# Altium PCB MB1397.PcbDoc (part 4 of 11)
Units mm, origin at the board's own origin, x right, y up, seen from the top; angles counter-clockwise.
Board outline 118.24 x 172.86 mm, 6 copper layers (Top Layer, L2_GND, L3_VCC, L4_SIG, L5_GND, Bottom Layer), stack 1.631 mm thick; 819 components, 632 nets, 2875 pads, 1523 vias.
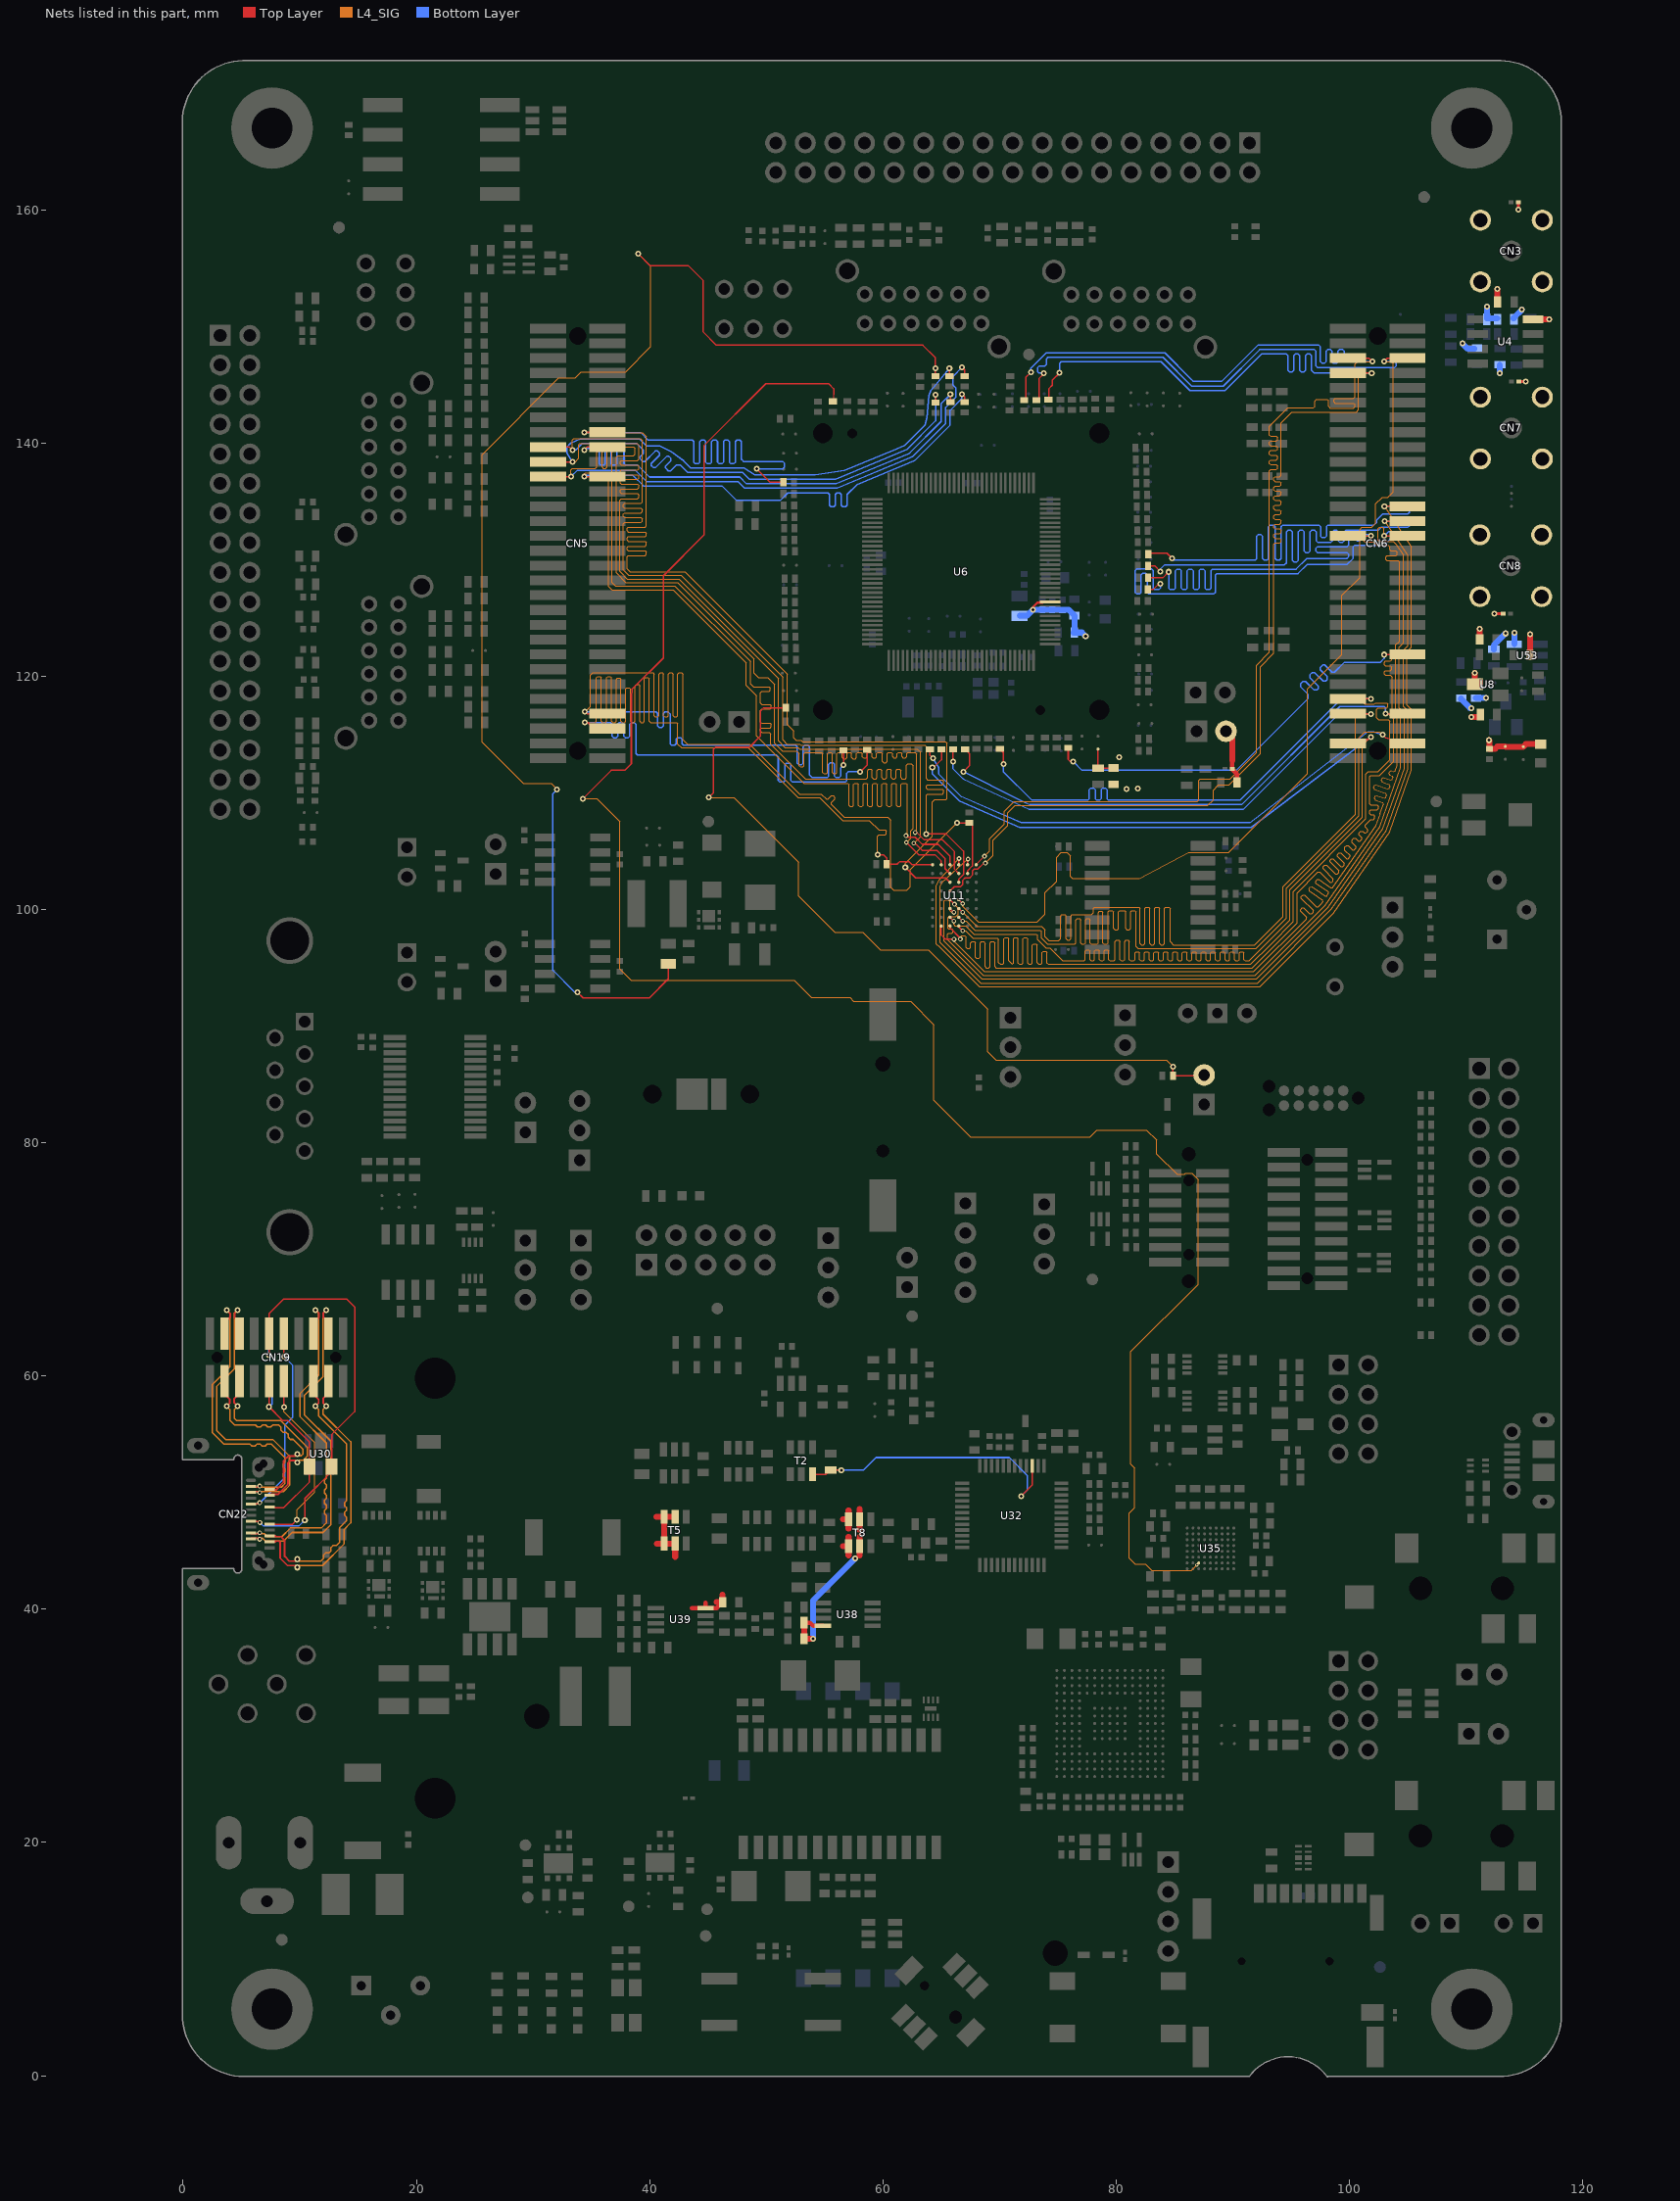
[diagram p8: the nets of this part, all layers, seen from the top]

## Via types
v1: diameter 0.508, hole 0.254, Top Layer to Bottom Layer, tented both sides, 1330 vias
v2: diameter 0.406, hole 0.203, Top Layer to Bottom Layer, tented both sides, 115 vias
v3: diameter 0.508, hole 0.254, Top Layer to Bottom Layer, 33 vias
v4: diameter 0.305, hole 0.152, Top Layer to Bottom Layer, tented both sides, 26 vias
v5: diameter 0.61, hole 0.305, Top Layer to Bottom Layer, tented both sides, 14 vias
v6: diameter 0.61, hole 0.33, Top Layer to Bottom Layer, tented both sides, 2 vias
v7: diameter 0.381, hole 0.203, Top Layer to Bottom Layer, tented both sides, 2 vias
v8: diameter 0.508, hole 0.203, Top Layer to Bottom Layer, tented both sides, 1 vias

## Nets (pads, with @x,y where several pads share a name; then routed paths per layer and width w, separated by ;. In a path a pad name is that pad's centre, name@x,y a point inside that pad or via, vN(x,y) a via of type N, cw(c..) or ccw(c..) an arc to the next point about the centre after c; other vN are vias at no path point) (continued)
A0: CN6.51 R136.2 U11.A3 | length 122.2
  Top Layer w0.127: U11.A3@66.499,98.585 66.5,98.504 v2(66.832,98.171) ; R136.2@70.029,113.765 70.33,113.462 v1(70.33,112.469) ; CN6.51@99.865,118.061 v1(101.826,118.059)
  L4_SIG w0.102: v2(66.832,98.171) 67.102,98.171 67.739,97.533 69.822,97.533 69.924,97.432 69.924,95.425 70.051,95.298 70.279,95.298 70.381,95.4 70.381,97.483 70.482,97.584 70.686,97.584 70.787,97.483 70.787,95.603 71.092,95.298 71.194,95.4 71.194,97.483 71.295,97.584 71.498,97.584 71.6,97.483 71.6,95.4 71.702,95.298 71.905,95.298 72.006,95.4 72.006,97.483 72.108,97.584 72.311,97.584 72.413,97.483 72.413,95.4 72.514,95.298 72.718,95.298 72.819,95.4 72.819,96.949 72.921,97.051 73.124,97.051 73.226,96.949 73.226,95.425 73.353,95.298 73.556,95.298 73.657,95.4 73.657,96.314 73.759,96.416 73.962,96.416 74.064,96.314 74.064,95.4 74.165,95.298 91.539,95.298 93.279,97.036 95.197,98.953 95.197,101.547 101.42,107.77 101.42,111.63 101.597,111.808 102.436,111.808 103.477,112.85 103.477,116.126 103.35,116.253 102.486,116.253 102.309,116.431 102.309,117.168 102.436,117.295 103.198,117.295 103.299,117.396 103.299,117.599 103.198,117.701 102.232,117.701 102.131,117.599 101.318,117.599 101.216,117.701 101.216,117.955 101.321,118.059 v1(101.826,118.059)
  Bottom Layer w0.127: v1(70.33,112.469) 70.33,111.808 72.768,109.37 77.564,109.37 77.691,109.497 77.691,110.284 77.818,110.411 78.072,110.411 78.199,110.284 78.199,109.497 78.326,109.37 78.58,109.37 78.707,109.497 78.707,110.284 78.834,110.411 79.088,110.411 79.215,110.284 79.215,109.497 79.342,109.37 90.602,109.37 99.291,118.059 v1(101.826,118.059)
A1: CN6.54 R138.2 U11.A4 | length 123
  Top Layer w0.127: U11.A4@65.749,98.585 65.748,98.438 66.634,97.551 v2(66.634,97.47) ; v1(66.901,111.808) 67.409,112.316 67.409,113.378 67.038,113.749 R138.2@67.039,113.748 ; v1(103.096,116.789) CN6.54@104.965,116.791
  L4_SIG w0.102: v2(66.634,97.47) 66.634,97.66 66.736,97.762 67.003,97.762 67.114,97.65 67.114,96.746 67.216,96.644 67.419,96.644 67.521,96.746 67.521,97.127 67.622,97.229 67.826,97.229 67.927,97.127 67.927,95.908 68.029,95.806 68.232,95.806 68.334,95.908 68.334,97.127 68.435,97.229 68.638,97.229 68.765,97.102 68.765,95.095 68.867,94.993 69.07,94.993 69.172,95.095 69.172,97.127 69.273,97.229 69.492,97.229 69.593,97.127 69.593,95.095 69.695,94.993 91.666,94.993 95.501,98.826 95.501,101.42 97.279,103.198 97.437,103.198 98.316,102.319 98.458,102.319 98.57,102.431 98.603,102.479 98.603,102.634 97.744,103.492 97.744,103.662 97.887,103.805 98.031,103.805 98.801,103.035 98.946,103.035 99.075,103.165 99.075,103.335 98.318,104.092 98.318,104.237 98.443,104.361 98.588,104.361 99.263,103.685 99.408,103.685 99.532,103.81 99.538,103.817 99.538,103.96 98.946,104.554 98.946,104.696 99.09,104.841 99.245,104.841 99.753,104.333 99.898,104.333 99.898,104.336 100.04,104.539 100.04,104.62 99.609,105.054 99.609,105.349 99.746,105.486 99.891,105.486 100.254,105.12 100.399,105.12 100.541,105.265 100.541,105.41 100.203,105.748 100.203,105.943 100.366,106.106 100.533,106.106 100.769,105.87 100.914,105.87 101.056,106.012 101.056,106.157 100.81,106.406 100.81,106.55 100.957,106.698 101.128,106.698 101.275,106.553 101.417,106.553 101.509,106.642 101.562,106.718 101.562,106.84 101.343,107.058 101.343,107.231 101.826,107.714 102.055,107.714 102.156,107.815 102.156,108.019 102.055,108.12 101.826,108.12 101.724,108.222 101.724,108.45 101.826,108.552 102.372,108.552 102.461,108.638 102.474,108.676 102.474,108.857 102.372,108.958 101.826,108.958 101.724,109.06 101.724,111.402 101.826,111.503 102.563,111.503 103.782,112.723 103.782,116.357 103.35,116.789 v1(103.096,116.789)
  Bottom Layer w0.127: v1(66.901,111.808) 71.643,109.416 72.573,108.989 90.76,108.989 99.17,117.399 102.969,117.399 103.096,117.272 v1(103.096,116.789)
A2: CN6.46 R132.2 U11.A5 | length 120.5
  Top Layer w0.127: U11.A5@64.999,98.585 64.999,97.81 65.364,97.445 v2(66.088,97.445) ; R132.2@75.888,113.85 75.888,112.855 76.045,112.697 v1(76.299,112.697) ; v1(102.984,121.857) 102.997,121.869 CN6.46@104.965,121.871
  L4_SIG w0.102: v2(66.088,97.445) 66.088,97.29 68.692,94.689 91.793,94.689 96.302,99.197 96.302,99.339 95.806,99.837 95.806,99.997 95.941,100.132 96.086,100.132 96.563,99.654 96.759,99.654 96.891,99.784 96.891,99.929 95.865,100.952 95.865,101.097 96.009,101.242 96.152,101.242 97.165,100.228 97.333,100.228 97.574,100.47 97.706,100.658 97.678,100.818 96.533,101.615 96.507,101.755 96.624,101.923 96.766,101.948 97.92,101.143 98.062,101.168 98.186,101.346 98.153,101.534 97.122,102.253 97.122,102.431 97.259,102.568 97.379,102.568 98.377,101.874 98.555,101.874 102.283,107.218 102.639,108.227 102.636,108.227 102.913,109.004 102.837,109.164 102.199,109.39 102.136,109.52 102.205,109.71 102.334,109.774 102.994,109.54 103.124,109.604 103.182,109.771 103.091,109.964 102.131,110.305 102.07,110.432 102.138,110.625 102.268,110.686 103.264,110.335 103.406,110.404 103.454,110.538 103.368,110.719 102.791,110.924 102.728,111.051 102.796,111.244 102.926,111.305 103.541,111.089 103.67,111.153 103.726,111.305 103.662,111.435 103.441,111.511 103.381,111.641 103.449,111.834 103.579,111.895 103.8,111.818 103.929,111.879 104.087,112.329 104.087,116.609 103.655,117.041 103.655,119.931 103.508,120.079 103.096,120.079 102.994,120.18 102.994,120.383 103.096,120.485 103.508,120.485 103.609,120.587 103.609,120.79 103.508,120.891 103.096,120.891 102.994,120.993 102.994,121.196 103.096,121.298 103.508,121.298 103.609,121.399 103.609,121.752 103.508,121.854 v1(102.984,121.857)
  Bottom Layer w0.127: v1(76.299,112.697) 77.066,111.93 90.303,111.93 96.463,118.09 96.463,118.446 95.796,119.113 95.796,119.331 96.008,119.543 96.241,119.543 96.962,118.821 97.194,118.821 97.312,118.939 97.312,119.175 96.596,119.891 96.596,120.106 96.784,120.294 97.028,120.294 97.739,119.583 97.956,119.583 98.095,119.722 98.095,119.964 97.495,120.564 97.495,120.749 97.724,120.978 97.869,120.978 98.501,120.345 98.718,120.345 99.579,121.206 102.653,121.206 102.984,121.538 v1(102.984,121.857)
A3: CN6.58 R139.2 U11.B3 | length 123.1
  Top Layer w0.127: R139.2@64.028,113.723 64.028,113.233 v1(64.285,112.977) ; U11.B3@66.499,99.335 v2(66.832,99.002) ; v1(102.842,114.983) 103.096,114.729 CN6.58@104.965,114.249
  L4_SIG w0.102: v2(66.832,99.002) 67.135,99.002 67.902,98.235 73.464,98.235 73.581,98.118 73.581,97.533 74.089,97.025 76.449,97.025 76.551,97.127 76.551,99.108 76.652,99.21 76.855,99.21 76.957,99.108 76.957,97.127 77.059,97.025 77.262,97.025 77.363,97.127 77.363,99.108 77.465,99.21 77.668,99.21 77.77,99.108 77.77,97.127 77.871,97.025 78.356,97.025 78.458,97.127 78.458,99.743 78.56,99.845 78.763,99.845 78.864,99.743 78.864,97.127 78.966,97.025 79.195,97.025 79.296,97.127 79.296,99.794 79.398,99.896 79.652,99.896 79.753,99.794 79.753,98.372 79.88,98.245 80.109,98.245 80.211,98.346 80.211,99.794 80.312,99.896 80.719,99.896 80.82,99.794 80.82,98.372 80.922,98.27 81.125,98.27 81.227,98.372 81.227,99.794 81.328,99.896 81.582,99.896 81.684,99.794 81.684,96.848 81.862,96.67 91.996,96.67 94.587,99.261 94.587,101.826 100.81,108.047 100.81,114.729 101.318,115.237 102.588,115.237 v1(102.842,114.983)
  Bottom Layer w0.127: v1(64.285,112.977) 64.767,112.189 64.767,111.625 66.695,109.698 71.854,107.439 91.478,107.439 101.572,115.237 102.08,115.237 v1(102.842,114.983)
A4: CN6.57 R140.2 U11.B4 | length 124.3
  Top Layer w0.127: v1(64.234,112.177) 64.348,112.177 65.016,112.845 R140.2@65.016,113.723 ; U11.B4@65.749,99.335 65.75,99.334 v2(66.083,99.002) ; CN6.57@99.865,114.251 100.965,114.249 101.318,114.602 101.636,114.602 v1(101.826,114.793)
  L4_SIG w0.102: v2(66.083,99.002) 66.083,98.704 66.185,98.603 67.102,98.603 67.815,97.889 73.152,97.889 73.251,97.79 73.251,97.432 73.962,96.721 74.292,96.721 75.41,95.603 77.239,95.603 77.34,95.705 77.34,96.441 77.442,96.543 77.645,96.543 77.747,96.441 77.747,95.705 77.848,95.603 78.052,95.603 78.153,95.705 78.153,96.441 78.255,96.543 78.458,96.543 78.56,96.441 78.56,95.705 78.661,95.603 78.864,95.603 78.966,95.705 78.966,96.441 79.068,96.543 79.271,96.543 79.372,96.441 79.372,95.705 79.474,95.603 79.814,95.603 79.916,95.705 79.916,97.254 80.018,97.356 80.221,97.356 80.322,97.254 80.322,95.705 80.424,95.603 80.627,95.603 80.729,95.705 80.729,97.254 80.83,97.356 81.034,97.356 81.135,97.254 81.135,95.705 81.237,95.603 81.504,95.603 81.605,95.705 81.605,96.263 81.707,96.365 81.91,96.365 82.012,96.263 82.012,95.705 82.113,95.603 82.316,95.603 82.418,95.705 82.418,96.263 82.52,96.365 82.723,96.365 82.824,96.263 82.824,95.705 82.926,95.603 83.129,95.603 83.231,95.705 83.231,96.263 83.332,96.365 83.536,96.365 83.637,96.263 83.637,95.705 83.739,95.603 83.942,95.603 84.044,95.705 84.044,96.263 84.145,96.365 84.348,96.365 84.45,96.263 84.45,95.705 84.552,95.603 84.755,95.603 84.856,95.705 84.856,96.263 84.958,96.365 85.161,96.365 85.263,96.263 85.263,95.705 85.364,95.603 85.568,95.603 85.669,95.705 85.669,96.263 85.771,96.365 85.974,96.365 86.076,96.263 86.076,95.705 86.177,95.603 86.38,95.603 86.482,95.705 86.482,96.263 86.584,96.365 86.787,96.365 86.888,96.263 86.888,95.705 86.99,95.603 87.193,95.603 87.295,95.705 87.295,96.263 87.396,96.365 87.6,96.365 87.701,96.263 87.701,95.705 87.803,95.603 88.006,95.603 88.108,95.705 88.108,96.263 88.209,96.365 88.412,96.365 88.514,96.263 88.514,95.705 88.616,95.603 88.819,95.603 88.92,95.705 88.92,96.263 89.022,96.365 89.225,96.365 89.327,96.263 89.327,95.705 89.428,95.603 89.632,95.603 89.733,95.705 89.733,96.263 89.835,96.365 90.038,96.365 90.14,96.263 90.14,95.705 90.241,95.603 90.444,95.603 90.546,95.705 90.546,96.263 90.648,96.365 90.851,96.365 90.952,96.263 90.952,95.705 91.054,95.603 91.415,95.603 94.892,99.08 94.892,101.699 101.115,107.922 101.115,114.079 v1(101.826,114.793)
  Bottom Layer w0.127: v1(64.234,112.177) 64.234,111.62 66.553,109.301 71.727,107.033 91.575,107.033 v1(101.826,114.793)
A5: CN6.53 R137.2 U11.C3 | length 123.4
  Top Layer w0.127: v1(66.015,112.697) R137.2@66.015,113.748 ; U11.C3@66.499,100.085 66.5,100.086 v2(66.832,99.753) ; CN6.53@99.865,116.791 101.798,116.789 v1(101.826,116.761)
  L4_SIG w0.102: v2(66.832,99.753) 68.044,98.539 73.591,98.539 73.886,98.245 73.886,97.66 74.216,97.33 75.08,97.33 75.232,97.483 75.232,99.438 75.334,99.54 75.603,99.54 75.705,99.438 75.705,97.483 75.806,97.381 76.01,97.381 76.111,97.483 76.111,99.438 76.213,99.54 77.874,99.54 78.052,99.718 78.052,100.099 78.153,100.2 81.945,100.2 82.047,100.099 82.047,97.076 82.149,96.975 82.352,96.975 82.453,97.076 82.453,100.099 82.555,100.2 82.786,100.2 82.888,100.099 82.888,97.076 82.989,96.975 83.193,96.975 83.294,97.076 83.294,100.099 83.396,100.2 83.624,100.2 83.726,100.099 83.726,97.076 83.828,96.975 84.031,96.975 84.132,97.076 84.132,100.099 84.234,100.2 84.529,100.2 84.63,100.099 84.63,97.229 84.884,96.975 91.869,96.975 94.282,99.388 94.282,101.951 100.505,108.174 100.505,116.456 100.81,116.761 v1(101.826,116.761)
  Bottom Layer w0.127: v1(66.015,112.697) 66.015,112.06 66.901,111.173 72.489,108.608 89.99,108.608 90.914,108.608 98.778,116.472 99.068,116.761 v1(101.826,116.761)
A6: CN6.30 R93.2 U11.C4 | length 122.1
  Top Layer w0.127: U11.C4@65.749,100.085 65.75,100.086 v2(66.083,99.753) ; R93.2@82.712,127.455 83.182,127.455 83.665,127.937 v1(83.792,127.937) ; v1(102.969,132.029) CN6.30@104.965,132.031
  L4_SIG w0.102: v2(66.083,99.753) 65.86,99.753 65.733,99.88 65.733,100.708 65.606,100.835 65.334,100.835 65.225,100.726 65.225,97.29 68.463,94.054 92.022,94.054 98.176,100.208 102.885,106.959 104.696,112.093 104.696,116.863 104.264,117.295 104.264,122.502 104.62,122.857 104.62,130.371 103.998,131.303 103.756,131.544 102.563,131.544 102.461,131.646 102.461,132.636 102.588,132.763 102.842,132.763 102.969,132.636 v1(102.969,132.029)
  Bottom Layer w0.127: v1(83.792,127.937) 83.792,127.556 83.665,127.429 83.284,127.429 83.157,127.556 83.157,129.08 83.03,129.207 81.755,129.207 81.633,129.085 81.633,127.175 81.76,127.048 82.014,127.048 82.141,127.175 82.141,128.699 82.268,128.826 82.522,128.826 82.649,128.699 82.649,127.175 82.776,127.048 88.364,127.048 88.504,127.188 88.504,128.674 88.631,128.801 95.583,128.801 96.37,129.588 99.794,129.588 100.322,130.117 100.322,131.112 100.449,131.239 102.969,131.239 103.477,131.747 104.874,131.747 105.001,131.874 105.001,132.255 104.874,132.382 103.322,132.382 v1(102.969,132.029)
A7: CN6.29 R89.2 U11.D4 | length 122.2
  Top Layer w0.127: U11.D4@65.749,100.835 65.75,100.835 v2(66.134,100.449) ; R89.2@82.742,128.441 83.99,128.44 v1(84.503,128.953) ; CN6.29@99.865,132.031 v1(101.826,132.029)
  L4_SIG w0.102: v2(66.134,100.449) 66.469,100.114 66.469,99.591 66.266,99.388 65.656,99.388 65.557,99.289 65.557,98.4 65.606,98.351 65.91,98.351 66.012,98.25 66.012,98.047 65.91,97.945 65.606,97.945 65.527,97.866 65.527,97.419 65.661,97.285 68.59,94.358 91.895,94.358 97.912,100.376 102.621,107.125 104.391,112.144 104.391,116.736 103.96,117.168 103.96,122.679 104.29,123.01 104.29,129.791 104.163,129.918 103.218,129.918 103.116,130.02 103.116,130.223 103.218,130.325 103.985,130.325 104.092,130.432 104.092,130.614 103.95,130.757 103.553,130.757 103.452,130.858 103.452,131.112 103.327,131.239 102.385,131.239 102.105,131.519 101.318,131.519 101.191,131.646 101.191,131.9 101.321,132.029 v1(101.826,132.029)
  Bottom Layer w0.127: v1(84.503,128.953) 84.503,127.556 84.63,127.429 84.948,127.429 85.075,127.556 85.075,129.055 85.202,129.182 85.456,129.182 85.583,129.055 85.583,127.556 85.71,127.429 85.964,127.429 86.091,127.556 86.091,129.055 86.218,129.182 86.472,129.182 86.599,129.055 86.599,127.556 86.726,127.429 86.98,127.429 87.107,127.556 87.107,129.055 87.234,129.182 87.488,129.182 87.615,129.055 87.615,127.556 87.742,127.429 87.996,127.429 88.123,127.556 88.123,129.055 88.25,129.182 95.425,129.182 96.34,130.096 99.764,130.096 99.941,130.277 99.941,130.457 99.794,130.604 97.254,130.604 97.127,130.731 97.127,130.985 97.254,131.112 99.794,131.112 99.921,131.239 99.921,132.001 100.048,132.128 100.396,132.128 100.523,132.001 100.523,131.747 100.65,131.62 100.904,131.62 101.031,131.747 101.031,132.001 101.158,132.128 101.727,132.128 v1(101.826,132.029)
A8: CN6.28 R88.2 U11.H2 | length 124.6
  Top Layer w0.127: U11.H2@67.249,103.835 67.249,104.282 v2(67.295,104.328) ; R88.2@82.737,129.457 83.315,129.456 v1(83.792,128.979) ; v1(103.033,133.299) CN6.28@104.965,133.301
  L4_SIG w0.102: v2(67.295,104.328) 65.072,102.324 64.92,101.94 64.92,97.155 68.374,93.698 92.098,93.698 98.443,100.046 103.149,106.792 105.001,112.039 105.001,117.015 104.62,117.396 104.62,122.222 105.001,122.603 105.001,130.35 v1(103.033,133.299)
  Bottom Layer w0.127: v1(83.792,128.979) 83.792,129.192 84.163,129.563 94.435,129.563 94.587,129.715 94.587,132.382 94.714,132.509 94.981,132.509 95.108,132.382 95.108,129.936 95.235,129.809 95.489,129.809 95.616,129.936 95.616,132.382 95.743,132.509 95.997,132.509 96.124,132.382 96.124,130.731 96.251,130.604 96.505,130.604 96.632,130.731 96.632,132.382 96.759,132.509 97.013,132.509 97.14,132.382 97.14,131.62 97.267,131.493 98.397,131.493 98.524,131.62 98.524,132.382 98.651,132.509 98.905,132.509 99.032,132.382 99.032,131.62 99.159,131.493 99.413,131.493 99.54,131.62 99.54,132.382 99.667,132.509 102.461,132.509 102.715,132.763 105.001,132.763 105.128,132.89 105.128,133.144 104.973,133.299 v1(103.033,133.299)
A9: CN6.26 R87.2 U11.H3 | length 126.6
  Top Layer w0.127: U11.H3@66.499,103.835 66.5,104.346 v2(66.52,104.366) ; R87.2@82.755,130.468 82.756,130.467 82.842,130.553 84.351,130.553 v1(84.808,130.096) ; v1(102.994,134.569) CN6.26@104.965,134.571
  L4_SIG w0.102: v2(66.52,104.366) 64.806,102.527 64.59,101.996 64.59,97.053 64.821,96.822 68.247,93.393 92.326,93.393 98.636,99.7 103.444,106.655 105.306,111.933 105.306,117.142 104.925,117.523 104.925,122.095 105.306,122.476 105.306,131.112 v1(102.994,134.569)
  Bottom Layer w0.127: v1(84.808,130.096) 84.935,129.969 91.92,129.969 92.047,130.096 92.047,132.001 92.174,132.128 92.428,132.128 92.555,132.001 92.555,130.096 92.682,129.969 92.936,129.969 93.063,130.096 93.063,132.827 93.19,132.954 93.508,132.954 93.635,132.827 93.635,130.096 93.762,129.969 94.016,129.969 94.143,130.096 94.143,132.827 94.27,132.954 97.394,132.954 97.521,132.827 97.521,132.001 97.648,131.874 97.902,131.874 98.029,132.001 98.029,132.827 98.156,132.954 102.083,132.954 102.334,133.205 102.334,133.398 102.842,133.906 105.001,133.906 105.128,134.033 105.128,134.414 104.973,134.569 v1(102.994,134.569)
A10: CN5.22 R48.2 U11.H4 | length 124.2
  Top Layer w0.127: v1(34.389,137.112) 36.386,137.112 CN5.22@36.385,137.111 ; v2(61.973,106.335) 61.986,106.335 62.123,106.195 62.766,106.195 63.376,105.585 64.742,105.585 65.748,104.582 U11.H4@65.749,103.835 ; v1(66.761,144.168) 66.774,144.168 67.003,143.942 R48.2@67.003,143.524
  L4_SIG w0.102: v1(34.389,137.112) 34.389,137.335 34.491,137.437 36.345,137.437 36.472,137.31 36.472,127.683 36.751,127.404 42.034,127.404 48.283,121.155 48.283,119.2 49.146,118.336 49.146,114.907 53.236,110.818 56.982,110.818 57.084,110.716 57.084,108.938 57.186,108.836 57.389,108.836 57.49,108.938 57.49,110.716 57.592,110.818 57.795,110.818 57.897,110.716 57.897,108.938 57.998,108.836 58.202,108.836 58.303,108.938 58.303,110.716 58.405,110.818 58.608,110.818 58.71,110.716 58.71,108.938 58.811,108.836 59.014,108.836 59.116,108.938 59.116,110.716 59.218,110.818 59.421,110.818 59.522,110.716 59.522,108.938 59.624,108.836 59.827,108.836 59.929,108.938 59.929,110.716 60.03,110.818 60.234,110.818 60.335,110.716 60.335,108.938 60.437,108.836 60.64,108.836 60.742,108.938 60.742,110.716 60.843,110.818 61.046,110.818 61.148,110.716 61.148,108.938 61.25,108.836 61.453,108.836 61.554,108.938 61.554,110.716 61.656,110.818 61.973,110.818 62.075,110.716 62.075,106.436 v2(61.973,106.335)
  Bottom Layer w0.127: v1(34.389,137.112) 34.486,137.208 38.58,137.208 39.469,136.319 46.2,136.319 47.445,135.075 51.204,135.075 51.839,135.71 55.281,135.71 55.408,135.583 55.408,134.668 55.535,134.541 55.789,134.541 55.916,134.668 55.916,135.583 56.043,135.71 56.297,135.71 56.424,135.583 56.424,134.668 56.551,134.541 56.805,134.541 56.932,134.668 56.932,135.583 57.788,136.439 62.71,138.478 65.758,141.526 65.758,142.796 66.761,143.8 v1(66.761,144.168)
A11: CN5.21 R28.2 U11.H5 | length 121.6
  Top Layer w0.127: CN5.21@31.285,137.111 33.244,137.109 v1(33.246,137.112) ; v2(62.012,105.75) 63.063,104.696 64.455,104.696 64.999,104.155 U11.H5@64.999,103.835 ; v1(66.774,146.479) 67.003,146.253 R28.2@67.003,145.738
  L4_SIG w0.102: v1(33.246,137.112) 33.246,137.701 33.373,137.828 35.354,137.828 35.456,137.93 35.456,139.207 35.593,139.344 35.809,139.344 35.928,139.225 35.928,137.93 36.03,137.828 36.236,137.828 36.335,137.93 36.335,139.273 36.406,139.344 36.675,139.344 36.777,139.243 36.777,128.039 37.081,127.734 42.161,127.734 48.638,121.257 48.638,119.352 48.892,119.098 50.239,119.098 50.34,118.996 50.34,118.793 50.239,118.692 49.604,118.692 49.502,118.59 49.502,117.686 49.604,117.584 50.315,117.584 50.416,117.483 50.416,117.279 50.315,117.178 49.604,117.178 49.502,117.076 49.502,116.083 49.604,115.981 50.315,115.981 50.416,115.88 50.416,115.677 50.315,115.575 49.604,115.575 49.502,115.473 49.502,115.288 49.629,115.161 50.239,115.161 50.366,115.034 50.366,114.17 53.337,111.199 58.58,111.199 58.682,111.3 58.682,111.91 58.783,112.011 58.986,112.011 59.088,111.91 59.088,111.3 59.19,111.199 59.393,111.199 59.494,111.3 59.494,111.91 59.596,112.011 59.799,112.011 59.901,111.91 59.901,111.3 60.002,111.199 60.206,111.199 60.307,111.3 60.307,111.91 60.409,112.011 60.612,112.011 60.714,111.91 60.714,111.3 60.815,111.199 61.018,111.199 61.12,111.3 61.12,111.91 61.222,112.011 61.425,112.011 61.526,111.91 61.526,111.3 61.628,111.199 61.923,111.199 62.024,111.3 62.024,112.367 62.151,112.494 62.431,112.494 62.583,112.342 62.583,106.962 62.38,106.759 62.38,106.119 v2(62.012,105.75)
  Bottom Layer w0.127: v1(33.246,137.112) 33.802,137.668 38.755,137.668 39.723,136.7 47.567,136.7 48.151,136.116 56.017,136.116 56.078,136.141 56.083,136.141 62.319,138.737 62.504,138.814 65.377,141.686 65.377,143.05 66.266,143.939 66.266,144.711 66.012,144.963 66.012,145.717 v1(66.774,146.479)
A12: CN5.18 R50.2 U11.G3 | length 125
  Top Layer w0.127: v1(34.389,139.398) 34.641,139.649 CN5.18@36.385,139.651 ; v2(62.761,106.601) 62.901,106.601 63.533,105.966 65.121,105.966 66.139,104.95 66.139,103.444 66.5,103.086 U11.G3@66.499,103.085 ; R50.2@65.786,143.503 v1(65.786,144.16)
  L4_SIG w0.102: v1(34.389,139.398) 34.641,139.649 38.603,139.649 38.732,139.52 38.732,139.037 38.605,138.91 37.259,138.91 37.132,138.783 37.132,128.854 37.948,128.039 42.39,128.039 48.943,121.486 48.943,120.266 49.324,119.885 50.112,119.885 50.721,119.276 50.721,114.247 51.382,113.586 52.601,113.586 52.829,113.358 52.829,112.342 52.931,112.24 53.134,112.24 53.236,112.342 53.236,113.358 53.337,113.459 54.745,113.459 54.846,113.358 54.846,111.757 54.948,111.656 55.151,111.656 55.253,111.757 55.253,113.358 55.354,113.459 55.557,113.459 55.659,113.358 55.659,111.757 55.761,111.656 55.964,111.656 56.065,111.757 56.065,113.358 56.167,113.459 56.408,113.459 56.51,113.358 56.51,113.027 56.612,112.926 56.815,112.926 56.916,113.027 56.916,113.358 57.018,113.459 57.221,113.459 57.323,113.358 57.323,113.027 57.424,112.926 57.628,112.926 57.729,113.027 57.729,113.358 57.831,113.459 58.143,113.459 58.245,113.358 58.245,113.078 58.346,112.977 58.55,112.977 58.651,113.078 58.651,113.358 58.753,113.459 58.956,113.459 59.058,113.358 59.058,113.078 59.159,112.977 59.362,112.977 59.464,113.078 59.464,113.358 59.566,113.459 59.855,113.459 59.957,113.358 59.957,112.697 60.058,112.596 60.261,112.596 60.363,112.697 60.363,113.358 60.465,113.459 60.719,113.459 60.82,113.358 60.82,113.104 60.922,113.002 61.125,113.002 61.227,113.104 61.227,113.358 61.328,113.459 61.531,113.459 61.633,113.358 61.633,113.104 61.735,113.002 61.938,113.002 62.039,113.104 62.039,113.358 62.141,113.459 62.761,113.459 62.888,113.332 62.888,106.728 v2(62.761,106.601)
  Bottom Layer w0.127: v1(34.389,139.398) 34.516,139.525 35.55,139.525 35.677,139.398 35.677,138.224 35.804,138.097 36.058,138.097 36.185,138.224 36.185,139.398 36.312,139.525 36.566,139.525 36.693,139.398 36.693,138.224 36.82,138.097 37.074,138.097 37.201,138.224 37.201,139.398 37.328,139.525 37.673,139.525 37.798,139.398 37.798,138.245 37.945,138.097 38.966,138.097 39.982,137.081 47.724,137.081 48.308,136.497 55.941,136.497 56.002,136.522 56.007,136.522 62.184,139.093 62.288,139.136 64.996,141.846 64.996,143.37 v1(65.786,144.16)
A13: CN5.19 R27.2 U11.G4 | length 122.1
  Top Layer w0.127: CN5.19@31.285,138.381 33.371,138.379 v1(33.373,138.382) ; v2(62.634,105.687) 62.735,105.687 63.345,105.077 64.615,105.077 65.331,104.364 65.331,103.505 65.75,103.086 U11.G4@65.749,103.085 ; R27.2@65.703,145.738 v1(65.702,146.393)
  L4_SIG w0.102: v1(33.373,138.382) 33.607,138.382 33.909,138.684 33.909,139.852 34.011,139.954 38.908,139.954 39.063,139.799 39.063,138.605 38.961,138.504 37.564,138.504 37.462,138.402 37.462,138.199 37.564,138.097 38.961,138.097 39.063,137.996 39.063,137.792 38.961,137.691 37.564,137.691 37.462,137.589 37.462,137.386 37.564,137.284 38.961,137.284 39.063,137.183 39.063,136.98 38.961,136.878 37.564,136.878 37.462,136.776 37.462,136.573 37.564,136.472 38.961,136.472 39.063,136.37 39.063,136.167 38.961,136.065 37.564,136.065 37.462,135.964 37.462,135.76 37.564,135.659 38.961,135.659 39.063,135.557 39.063,135.329 38.936,135.202 37.564,135.202 37.437,135.075 37.437,128.981 38.072,128.344 42.517,128.344 51.051,119.809 51.051,114.45 51.613,113.889 52.726,113.889 52.851,113.764 62.939,113.764 63.218,113.485 63.218,106.22 62.685,105.687 v2(62.634,105.687)
  Bottom Layer w0.127: v1(33.373,138.382) 32.893,139.126 32.893,139.649 33.246,140.002 34.008,140.335 39.136,140.335 39.723,139.748 40.866,139.748 41.882,139.24 42.898,138.478 43.533,137.843 48.105,137.843 48.994,137.284 54.206,137.284 56.693,137.635 60.894,139.383 61.854,139.781 63.599,141.526 63.772,142.161 63.944,144.066 64.12,144.516 v1(65.702,146.393)
A14: CN5.17 R53.2 U11.F3 | length 125.3
  Top Layer w0.127: CN5.17@31.285,139.651 33.122,139.649 v1(33.373,139.398) ; v1(63.726,106.474) 65.425,106.474 66.901,105.001 66.901,102.994 66.5,102.593 U11.F3@66.499,102.335 ; R53.2@64.501,143.474 64.501,143.474 64.516,143.49 v1(64.516,144.145)
  L4_SIG w0.102: v1(33.373,139.398) 33.373,140.256 33.475,140.358 39.215,140.358 39.367,140.205 39.367,134.917 39.266,134.816 37.843,134.816 37.742,134.714 37.742,134.511 37.843,134.409 39.266,134.409 39.367,134.308 39.367,134.104 39.266,134.003 37.843,134.003 37.742,133.901 37.742,133.698 37.843,133.596 39.266,133.596 39.367,133.495 39.367,133.292 39.266,133.19 37.843,133.19 37.742,133.088 37.742,129.106 38.199,128.648 42.695,128.648 51.407,119.936 51.407,114.551 51.768,114.191 52.851,114.191 52.973,114.069 63.599,114.069 63.726,113.942 63.726,111.214 63.828,111.115 65.098,111.115 65.199,111.011 65.199,110.808 65.098,110.706 63.828,110.706 63.726,110.607 63.726,110.401 63.828,110.3 65.098,110.3 65.199,110.198 65.199,109.995 65.098,109.893 63.828,109.893 63.726,109.792 v1(63.726,106.474)
  Bottom Layer w0.127: v1(33.373,139.398) 33.658,139.398 34.214,139.954 38.882,139.954 39.469,139.367 39.469,139.113 39.177,138.821 39.177,138.641 39.406,138.412 39.586,138.412 40.485,139.314 40.665,139.314 40.846,139.134 40.846,138.953 40.137,138.245 40.137,138.064 40.315,137.886 40.495,137.886 41.458,138.849 41.638,138.849 41.819,138.669 41.819,138.488 41.364,138.034 41.364,137.853 41.603,137.615 41.78,137.615 42.263,138.097 42.644,138.097 43.279,137.462 47.978,137.462 48.562,136.878 55.865,136.878 55.926,136.903 55.931,136.903 62.073,139.459 64.516,141.905 v1(64.516,144.145)
A15: CN5.16 R68.2 U11.F4 | length 122.8
  Top Layer w0.127: v1(34.392,140.891) 34.42,140.919 CN5.16@36.385,140.921 ; v1(49.185,137.78) 50.34,136.627 R68.2@51.468,136.627 ; v1(61.923,103.604) 62.812,102.715 65.369,102.715 65.75,102.334 U11.F4@65.749,102.335
  L4_SIG w0.102: v1(34.392,140.891) 39.367,140.891 39.723,140.536 39.723,132.885 39.621,132.784 38.174,132.784 38.072,132.682 38.072,132.479 38.174,132.377 39.621,132.377 39.723,132.276 39.723,132.072 39.621,131.971 38.174,131.971 38.072,131.869 38.072,131.666 38.174,131.564 39.621,131.564 39.723,131.463 39.723,131.26 39.621,131.158 38.174,131.158 38.072,131.056 38.072,130.853 38.174,130.752 39.621,130.752 39.723,130.65 39.723,130.447 39.621,130.345 38.174,130.345 38.072,130.244 38.072,129.207 38.326,128.953 43.025,128.953 51.788,120.19 51.788,115.872 52.336,115.325 52.336,114.717 52.56,114.493 52.976,114.493 53.096,114.374 65.377,114.374 65.504,114.247 65.504,109.522 65.402,109.421 64.437,109.421 64.234,109.217 64.234,106.271 61.923,103.96 v1(61.923,103.604)
  Bottom Layer w0.127: v1(34.392,140.891) 39.215,140.891 39.85,140.256 43.66,140.256 43.787,140.129 43.787,138.351 43.914,138.224 44.168,138.224 44.295,138.351 44.295,140.129 44.422,140.256 44.676,140.256 44.803,140.129 44.803,138.351 44.93,138.224 45.184,138.224 45.311,138.351 45.311,140.129 45.438,140.256 45.692,140.256 45.819,140.129 45.819,138.351 45.946,138.224 46.2,138.224 46.327,138.351 46.327,140.129 46.454,140.256 46.708,140.256 46.835,140.129 46.835,138.351 46.962,138.224 47.216,138.224 47.343,138.351 47.343,140.129 47.47,140.256 47.724,140.256 47.851,140.129 47.851,138.605 48.042,138.415 51.407,138.415 51.534,138.288 51.534,137.907 51.407,137.78 v1(49.185,137.78)
A16: CN6.7 R39.2 U11.E4 | length 122.9
  Top Layer w0.127: U11.E4@65.749,101.585 66.116,101.953 66.647,101.953 66.85,102.156 66.85,102.512 67.053,102.715 67.434,102.715 67.663,102.944 67.663,103.299 67.841,103.477 68.146,103.477 68.654,103.985 v2(68.781,103.985) ; R39.2@74.247,143.607 74.247,144.681 74.521,144.955 74.521,145.387 75.143,146.009 v1(75.143,146.035) ; CN6.7@99.865,146.001 99.865,146.002 v1(101.902,146.002)
  L4_SIG w0.102: v2(68.781,103.985) 69.441,104.645 69.441,105.926 70.711,107.196 70.711,108.278 71.346,108.913 87.831,108.913 88.323,109.403 88.323,110.244 88.755,110.673 89.667,110.673 92.37,113.375 92.37,120.818 93.52,121.968 93.52,131.315 93.622,131.417 94.028,131.417 94.13,131.519 94.13,131.722 94.028,131.823 93.622,131.823 93.52,131.925 93.52,132.128 93.622,132.23 94.028,132.23 94.13,132.331 94.13,132.535 94.028,132.636 93.622,132.636 93.52,132.738 93.52,132.941 93.622,133.043 94.028,133.043 94.13,133.144 94.13,133.347 94.028,133.449 93.622,133.449 93.52,133.551 93.52,133.754 93.622,133.855 94.028,133.855 94.13,133.957 94.13,134.16 94.028,134.262 93.622,134.262 93.52,134.363 93.52,134.567 93.622,134.668 94.028,134.668 94.13,134.77 94.13,134.973 94.028,135.075 93.622,135.075 93.52,135.176 93.52,135.379 93.622,135.481 94.028,135.481 94.13,135.583 94.13,135.786 94.028,135.887 93.622,135.887 93.52,135.989 93.52,136.192 93.622,136.294 94.028,136.294 94.13,136.395 94.13,136.599 94.028,136.7 93.622,136.7 93.52,136.802 93.52,137.005 93.622,137.107 94.028,137.107 94.13,137.208 94.13,141.704 95.07,142.644 100.581,142.644 100.785,142.847 100.785,145.768 101.018,146.002 v1(101.902,146.002)
  Bottom Layer w0.127: v1(75.143,146.035) 75.143,146.835 75.27,146.962 83.853,146.962 86.317,144.498 89.334,144.498 92.459,147.622 94.587,147.622 94.714,147.495 94.714,146.225 94.841,146.098 95.095,146.098 95.222,146.225 95.222,147.495 95.349,147.622 95.603,147.622 95.73,147.495 95.73,146.225 95.857,146.098 96.111,146.098 96.238,146.225 96.238,147.495 96.365,147.622 96.619,147.622 96.746,147.495 96.746,146.225 96.97,146.002 v1(101.902,146.002)
A17: CN6.6 R42.2 U11.D3 | length 122.8
  Top Layer w0.127: U11.D3@66.499,100.835 66.5,100.835 66.789,100.546 66.789,100.503 v2(66.832,100.503) ; R42.2@73.203,143.579 73.378,143.754 73.378,145.514 73.784,145.92 v1(73.784,145.997) ; v1(102.969,146.987) 103.254,147.272 104.965,147.272 CN6.6@104.965,147.271
  L4_SIG w0.102: v2(66.832,100.503) 66.832,100.277 68.179,98.93 73.226,98.93 73.911,99.616 73.911,101.445 74.889,102.423 74.889,104.48 75.283,104.874 75.791,104.874 76.07,104.595 76.07,102.842 76.248,102.664 81.989,102.664 86.205,104.874 89.629,104.874 96.39,111.636 96.39,118.897 99.347,121.854 99.347,126.931 100.884,128.469 100.884,132.568 101.08,132.763 101.902,132.763 102.258,133.119 102.258,134.795 102.817,135.354 103.274,135.354 103.731,135.811 103.731,146.835 103.579,146.987 v1(102.969,146.987)
  Bottom Layer w0.127: v1(73.784,145.997) 73.378,145.997 73.251,146.124 73.251,146.441 73.416,146.606 73.886,146.606 74.013,146.733 74.013,147.203 74.15,147.343 84.013,147.343 86.477,144.879 89.177,144.879 92.301,148.003 97,148.003 97.127,147.876 97.127,146.606 97.279,146.454 103.858,146.454 103.985,146.581 103.985,146.86 103.858,146.987 v1(102.969,146.987)
A18: CN6.5 R41.2 U11.H1 | length 123.6
  Top Layer w0.127: U11.H1@67.999,103.835 67.998,103.863 v2(68.704,104.569) ; R41.2@72.154,143.579 72.26,143.685 72.26,145.641 v1(72.692,146.073) ; CN6.5@99.865,147.271 99.865,147.272 101.671,147.272 v1(101.953,146.987)
  L4_SIG w0.102: v2(68.704,104.569) 69.136,105.001 69.136,106.053 70.406,107.323 70.406,108.405 71.244,109.243 86.942,109.243 87.094,109.395 87.094,111.084 87.196,111.186 89.748,111.186 92.024,113.462 92.024,120.932 93.139,122.047 93.139,137.625 93.241,137.726 93.723,137.726 93.825,137.828 93.825,138.031 93.723,138.133 93.241,138.133 93.139,138.234 93.139,138.438 93.241,138.539 93.723,138.539 93.825,138.641 93.825,138.844 93.723,138.946 93.241,138.946 93.139,139.047 93.139,139.25 93.241,139.352 93.723,139.352 93.825,139.454 93.825,139.657 93.723,139.758 93.241,139.758 93.139,139.86 93.139,140.063 93.241,140.165 93.723,140.165 93.825,140.266 93.825,140.47 93.723,140.571 93.241,140.571 93.139,140.673 93.139,141.425 94.739,143.025 96.924,143.025 97.025,143.126 97.025,143.584 97.178,143.736 98.092,143.736 98.194,143.634 98.194,143.152 98.346,142.999 100.353,142.999 100.454,143.101 100.454,143.304 100.353,143.406 98.753,143.406 98.651,143.507 98.651,143.711 98.753,143.812 100.302,143.812 100.454,143.965 100.454,146.759 100.683,146.987 v1(101.953,146.987)
  Bottom Layer w0.127: v1(72.692,146.073) 72.692,146.421 73.993,147.724 84.173,147.724 86.431,145.463 86.434,145.463 86.589,145.311 89.065,145.311 92.141,148.384 97.381,148.384 97.508,148.257 97.508,146.987 97.635,146.86 97.889,146.86 98.016,146.987 98.016,147.876 98.143,148.003 98.372,148.003 98.499,147.876 98.499,146.962 98.626,146.835 98.88,146.835 99.007,146.962 99.007,147.876 99.134,148.003 99.413,148.003 99.538,147.879 99.538,147.117 99.67,146.987 v1(101.953,146.987)
A19: CN5.54 R146.1 R156.2 U11.G2 | length 121.2
  Top Layer w0.127: v1(34.453,116.952) 34.615,116.789 CN5.54@36.385,116.791 ; v1(56.617,112.37) R146.1@56.617,113.652 ; v1(66.36,107.424) R156.2@67.409,107.424 ; U11.G2@67.249,103.085 67.249,103.317 67.663,103.731 67.663,107.17 R156.2@67.409,107.424 ; R156.2@67.41,107.422 R156.2@67.409,107.424
  L4_SIG w0.102: v1(34.453,116.952) 34.922,117.422 34.922,120.089 35.126,120.292 40.279,120.292 40.381,120.19 40.381,116.622 40.483,116.52 40.686,116.52 40.787,116.622 40.787,120.165 40.914,120.292 41.092,120.292 41.194,120.19 41.194,116.622 41.295,116.52 41.499,116.52 41.6,116.622 41.6,120.165 41.727,120.292 41.905,120.292 42.007,120.19 42.007,116.622 42.108,116.52 42.311,116.52 42.413,116.622 42.413,120.165 42.54,120.292 42.743,120.292 42.845,120.19 42.845,114.554 43.228,114.17 48.59,114.17 52.857,109.903 54.709,109.903 55.154,109.459 55.298,109.459 55.598,109.758 55.743,109.758 55.885,109.616 55.885,109.471 55.585,109.172 55.585,109.027 56.69,107.922 60.399,107.922 60.678,107.643 60.678,101.902 60.907,101.674 62.05,101.674 62.329,101.953 62.329,103.426 66.327,107.424 v1(66.36,107.424)
  Bottom Layer w0.127: v1(34.453,116.952) 40.549,116.952 40.676,116.825 40.676,115.745 40.803,115.618 41.057,115.618 41.184,115.745 41.184,116.825 41.311,116.952 41.565,116.952 41.755,116.761 41.755,114.221 41.882,114.094 42.139,114.094 42.266,114.221 42.266,114.602 42.393,114.729 42.647,114.729 42.774,114.602 42.774,114.221 42.901,114.094 52.525,114.094 52.652,113.967 52.652,112.555 52.779,112.428 53.033,112.428 53.16,112.555 53.16,113.967 53.287,114.094 53.566,114.094 53.693,113.967 53.693,111.554 53.947,111.3 55.217,111.3 55.344,111.427 55.344,112.443 55.471,112.57 55.725,112.57 55.852,112.443 55.852,111.427 55.979,111.3 56.233,111.3 56.36,111.427 56.36,112.113 v1(56.617,112.37)
A20: CN5.56 R143.1 R162.2 U11.H6 | length 122.2
  Top Layer w0.127: v1(34.44,116.025) 34.719,116.025 35.225,115.519 CN5.56@36.385,115.521 ; v1(58.036,111.783) 58.649,112.395 R143.1@58.649,113.688 ; v1(59.535,104.696) 60.043,104.696 60.315,104.424 R162.2@60.316,103.885 61.211,103.883 61.44,104.112 62.225,104.112 62.507,103.833 U11.H6@64.249,103.835
  L4_SIG w0.102: v1(34.44,116.025) 35.339,116.025 35.441,116.126 35.441,119.885 35.542,119.987 35.745,119.987 35.847,119.885 35.847,116.126 35.949,116.025 36.215,116.025 36.317,116.126 36.317,119.885 36.419,119.987 36.622,119.987 36.723,119.885 36.723,116.126 36.825,116.025 37.028,116.025 37.13,116.126 37.13,119.733 37.231,119.835 37.435,119.835 37.536,119.733 37.536,116.126 37.638,116.025 37.841,116.025 37.943,116.126 37.943,118.92 38.044,119.022 38.247,119.022 38.349,118.92 38.349,116.126 38.451,116.025 38.654,116.025 38.755,116.126 38.755,119.174 38.857,119.276 39.06,119.276 39.162,119.174 39.162,116.126 39.263,116.025 39.441,116.025 39.543,116.126 39.543,119.784 39.644,119.885 39.848,119.885 39.949,119.784 39.949,116.152 40.076,116.025 42.314,116.025 42.415,115.923 42.415,114.17 42.72,113.866 48.463,113.866 52.73,109.598 54.582,109.598 56.563,107.617 58.824,107.617 59.637,106.804 60.195,106.804 60.297,106.703 60.297,106.5 60.195,106.398 59.637,106.398 59.535,106.296 v1(59.535,104.696)
  Bottom Layer w0.127: v1(34.44,116.025) 36.642,116.025 36.769,115.898 36.769,114.856 36.896,114.729 37.15,114.729 37.277,114.856 37.277,115.898 37.404,116.025 37.666,116.025 37.793,115.898 37.793,114.856 37.92,114.729 38.174,114.729 38.301,114.856 38.301,115.898 38.428,116.025 38.682,116.025 38.834,115.872 38.834,113.383 38.961,113.256 50.848,113.256 51.026,113.078 51.026,111.046 51.153,110.919 51.473,110.919 51.6,111.046 51.6,112.428 51.727,112.555 51.981,112.555 52.108,112.428 52.108,111.046 52.235,110.919 56.769,110.919 56.896,111.046 56.896,111.681 57.023,111.808 58.011,111.808 v1(58.036,111.783)
ADC_OUTN: C35.1 R152.2 SB27.1 | length 3
  Top Layer w0.127: SB27.1@78.435,113.754 78.435,112.156 78.461,112.131 79.779,112.131 79.781,112.133 C35.1@79.781,112.133 ; R152.2@78.461,112.13 R152.2@78.461,112.13
AGND: C28.1 C30.1 C33.1 C35.2 C36.2 C158.1 C158.2 C159.1 C166.1 C167.2 C168.1 C169.1 C170.1 C171.1 C179.1 C180.1 CN3.2 CN3.3 CN3.4 CN3.5 CN7.2 CN7.3 CN7.4 CN7.5 CN8.2 CN8.3 CN8.4 CN8.5 CN9.2 L1.2 R19.1 R124.1 R301.2 R307.2 R311.1 SB30.2 SB31.2 U2.2 U4.4 U5.2 U6.42 U7.2 U8.3 U9.2 U53.5 | length 37.9
  Top Layer w0.203: v1(72.87,125.71) 72.87,125.93 73.255,126.314 U6.42@73.678,126.314
  Top Layer w0.254: v1(112.415,125.349) U7.2@113.191,125.349 ; v1(114.485,160.017) U2.2@114.485,160.655 ; U5.2@114.508,145.288 v1(115.113,145.288)
  Top Layer w0.381: 89.946,112.766 U9.2@89.947,112.042 90.361,111.625 C36.2@90.362,110.894
  Top Layer w0.508: CN9.2@89.417,115.279 89.946,114.747 89.946,112.766 ; v1(110.462,116.507) 111.042,116.507 R124.1@111.233,116.698 ; U8.3@110.759,119.301 v1(110.759,120.274) ; C28.1@111.158,123.175 v1(111.158,124.051) ; v1(111.963,114.51) 112.003,114.47 C33.1@112.003,113.785 112.489,113.785 112.684,113.979 SB30.2@113.365,113.979 113.384,113.96 SB31.2@114.907,113.96 115.126,114.179 L1.2@116.383,114.179 ; R19.1@112.682,152.067 v1(112.682,153.21) ; C30.1@115.471,121.808 v1(115.471,123.619) ; U4.4@115.735,150.607 v1(117.13,150.607)
  Bottom Layer w0.508: C166.1@71.727,125.181 72.342,125.181 v1(72.87,125.71) 75.923,125.71 76.134,125.498 76.424,125.206 76.426,125.204 76.426,123.807 76.365,123.746 77.061,123.746 v1(77.379,123.429) ; C180.1@109.573,118.095 109.573,118.031 110.335,117.269 v1(110.462,117.269) ; v1(109.675,148.537) 110.142,148.069 C159.1@110.716,148.069 ; C179.1@110.843,118.143 v1(111.724,118.143) ; v1(111.798,151.686) 111.798,150.67 C158.1@112.682,150.67 ; R311.1@112.367,122.288 R311.1@112.367,122.308 112.367,122.649 v1(113.383,123.665) ; v1(112.903,145.971) R307.2@112.903,146.703 ; C158.2@114.082,150.67 114.082,150.729 v1(114.788,151.432) ; U53.5@114.141,122.743 v1(114.14,123.741)
  other v1: 80.891,110.34 81.844,110.373 80.236,113.078
AMP_5V: C119.2 R267.2 T8.1 T8.2 T8.5 T8.6 U38.8 | length 19.7
  Top Layer w0.381: R267.2@53.239,38.851 53.754,38.849 54.013,38.59 U38.8@54.848,38.59
  Top Layer w0.508: R267.2@53.239,38.851 C119.2@53.239,37.472 v1(53.99,37.47) ; 56.573,45.408 T8.1@57.051,45.409 ; 56.573,47.709 T8.6@57.051,47.709 ; 57.051,44.63 T8.1@57.051,45.409 ; 57.051,46.187 T8.1@57.051,45.409 ; 57.051,46.932 T8.6@57.051,47.709 ; 57.051,48.486 T8.6@57.051,47.709 ; 58.001,44.63 T8.2@58.001,45.409 58.001,46.187 ; 58.001,46.794 T8.5@58.001,47.709 58.001,48.578
  Bottom Layer w0.508: v1(53.99,37.47) 53.99,40.731 v1(57.63,44.371)
AMP_VDD: C108.2 T5.1 T5.2 T5.5 T5.6 U39.8 | length 11
  Top Layer w0.381: 43.624,40.089 U39.8@44.78,40.091 ; 44.78,40.538 U39.8@44.78,40.091 ; C108.2@46.255,40.607 C108.2@46.255,40.607 ; C108.2@46.256,40.607 45.738,40.089 U39.8@44.78,40.091
  Top Layer w0.508: 40.582,47.93 T5.6@41.234,47.93 ; 40.593,45.63 T5.1@41.234,45.63 ; 42.184,44.504 T5.2@42.184,45.63 T5.1@41.234,45.63 ; T5.5@42.184,47.93 T5.6@41.234,47.93 ; 45.756,40.607 C108.2@46.255,40.607 ; C108.2@46.256,40.607 46.256,41.229 ; T5.1@41.234,45.63 T5.6@41.234,47.93
Audio_INT: R43.2 U35.G3 | length 170.5
  Top Layer w0.102: R43.2@55.702,143.571 55.776,143.645 55.776,144.145
  Top Layer w0.127: v1(34.262,109.497) 36.7,111.935 37.869,111.935 38.428,112.494 38.428,118.514 38.478,118.565 38.478,118.877 41.171,121.569 41.171,128.623 44.651,132.103 44.651,139.774 49.959,145.082 55.344,145.082 55.776,144.65 55.776,144.145 ; v4(86.916,43.805) U35.G3@87.077,43.966
  L4_SIG w0.102: v1(34.262,109.497) 35.481,109.497 37.437,107.541 37.437,94.917 38.428,93.927 52.398,93.927 53.871,92.453 57.173,92.453 57.49,92.136 62.366,92.136 64.376,90.128 64.376,83.622 67.508,80.49 77.747,80.49 78.356,81.1 82.603,81.1 83.462,80.241 83.462,79.04 85.213,77.29 85.862,77.29 85.962,77.39 86.507,77.39 87.043,76.854 87.043,67.873 81.252,62.082 81.252,52.423 81.582,52.093 81.582,48.715 81.125,48.257 81.125,44.371 81.633,43.863 82.522,43.863 83.053,43.332 86.444,43.332 v4(86.916,43.805)
BK_Drive: R26.1 R175.1 | length 121.3
  Top Layer w0.127: v1(33.805,92.911) 34.287,92.428 39.977,92.428 41.6,94.051 R175.1@41.6,95.322 ; v1(39.012,156.233) 40.053,155.191 43.33,155.191 44.564,153.957 44.564,149.543 45.723,148.384 63.421,148.384 64.501,147.305 v1(64.501,146.393) R26.1@64.501,145.738
  L4_SIG w0.102: v1(32.052,110.284) 31.544,110.792 29.182,110.792 25.651,114.323 25.651,139.012 32.21,145.57 33.607,145.57 34.135,146.098 37.945,146.098 40.104,148.257 40.104,155.141 v1(39.012,156.233)
  Bottom Layer w0.127: v1(32.052,110.284) 31.697,109.929 31.697,94.79 33.576,92.911 v1(33.805,92.911)
BOOT0: JP8.2 R123.1 R182.1 | length 69.9
  Top Layer w0.127: v1(45.057,109.598) 45.463,110.005 45.463,113.739 45.644,113.919 48.565,113.919 49.502,114.856 49.502,117.015 49.756,117.269 51.674,117.269 R123.1@51.674,117.299 ; v1(84.859,86.535) R182.1@84.86,85.75 87.475,85.748 JP8.2@87.538,85.81
  L4_SIG w0.102: v1(45.057,109.598) 47.216,109.598 52.778,104.037 52.778,101.167 55.89,98.054 58.252,98.054 59.764,96.543 63.878,96.543 68.984,91.437 68.984,87.805 69.705,87.084 84.313,87.084 v1(84.859,86.535)
C1_CC1: CN19.9 CN22.A5 SB122.1 U30.1 | length 16.8
  Top Layer w0.127: CN19.9@7.366,59.56 v1(7.366,57.353) 8.537,56.182 8.989,56.182 10.833,54.338 10.833,50.914 8.633,48.715 7.483,48.715 CN22.A5@7.414,48.783
  Bottom Layer w0.127: v1(7.366,57.353) 7.62,57.607 SB122.1@7.62,59.381
C1_CC2: CN19.10 CN22.B5 SB121.1 U30.2 | length 38
  Top Layer w0.127: CN22.B5@5.814,47.534 6.487,47.534 v2(6.591,47.429) ; v1(7.366,61.798) CN19.10@7.366,63.63 7.366,65.354 8.608,66.596 14.023,66.596 14.704,65.916 14.704,56.944 12.733,54.973 12.733,51.798 10.437,49.502 v1(10.437,47.648)
  Bottom Layer w0.127: v2(6.591,47.429) 6.855,47.165 9.954,47.165 v1(10.437,47.648) ; SB121.1@7.338,63.05 SB121.1@7.338,63.048 7.338,61.826 v1(7.366,61.798)
C1_RX1+: CN19.4 CN22.B11 | length 26.6
  Top Layer w0.155: CN19.4@3.556,63.63 3.556,64.572 4.021,65.037 4.021,65.357 v1(3.724,65.657) ; CN22.B11@5.816,50.534 5.875,50.472 6.477,50.472 v2(6.566,50.561)
  L4_SIG w0.13: v1(3.724,65.657) 4,65.38 4,60.775 2.512,59.286 2.512,55.136 3.472,54.176 5.723,54.176 5.9,53.998 6.159,53.998 6.337,54.176 6.596,54.176 6.774,53.998 7.033,53.998 7.211,54.176 7.536,54.176 8.735,52.977 8.735,52.603 8.583,52.451 8.583,52.192 8.735,52.04 8.735,51.78 8.583,51.628 8.583,51.369 8.735,51.217 8.735,50.775 8.432,50.472 6.655,50.472 v2(6.566,50.561)
C1_RX1-: CN19.6 CN22.B10 | length 26.7
  Top Layer w0.155: v1(4.661,65.657) 4.402,65.398 4.402,65.052 4.826,64.628 CN19.6@4.826,63.63 ; CN22.B10@5.816,50.034 5.875,50.091 6.477,50.091 v2(6.566,50.002)
  L4_SIG w0.13: v1(4.661,65.657) 4.381,65.378 4.381,60.617 2.893,59.129 2.893,55.293 3.63,54.557 7.694,54.557 9.116,53.134 9.116,50.618 8.59,50.091 6.655,50.091 v2(6.566,50.002)
C1_RX2+: CN19.17 CN22.A11 | length 24.6
  Top Layer w0.155: CN22.A11@7.416,45.784 7.919,45.784 7.978,45.843 8.204,45.843 8.317,45.731 8.317,44.377 8.948,43.746 9.606,43.746 v1(9.771,43.581) ; v1(12.278,57.407) 12.002,57.683 12.002,58.052 12.446,58.496 CN19.17@12.446,59.56
  L4_SIG w0.13: v1(9.771,43.581) 9.936,43.746 11.951,43.746 13.815,45.611 13.815,46.86 14.374,47.419 14.374,54.353 12.002,56.726 12.002,57.127 v1(12.278,57.407)
C1_RX2-: CN19.15 CN22.A10 | length 24.5
  Top Layer w0.155: CN22.A10@7.416,46.284 7.919,46.284 7.978,46.224 8.362,46.224 8.698,45.888 8.698,44.535 9.106,44.127 9.606,44.127 v1(9.771,44.293) ; CN19.15@11.176,59.56 11.176,58.44 11.62,57.996 11.62,57.683 v1(11.341,57.407)
  L4_SIG w0.13: v1(9.771,44.293) 9.936,44.127 11.793,44.127 12.029,44.364 12.029,44.643 12.212,44.826 12.492,44.826 12.675,45.009 12.675,45.288 12.857,45.471 13.137,45.471 13.434,45.768 13.434,47.018 13.993,47.577 13.993,47.902 13.84,48.054 13.84,48.313 13.993,48.466 13.993,48.725 13.84,48.877 13.84,49.136 13.993,49.289 13.993,54.196 11.62,56.568 11.62,57.127 v1(11.341,57.407)
C1_SBU1: CN19.11 CN22.A8 | length 16.1
  Top Layer w0.127: CN22.A8@7.414,47.282 9.36,47.282 v1(9.751,47.673) ; v1(8.636,57.325) CN19.11@8.636,59.56
  L4_SIG w0.102: v1(8.636,57.325) 8.636,56.916 11.275,54.277 11.275,50.061 9.751,48.537 v1(9.751,47.673)
C1_SBU2: CN19.12 CN22.B8 | length 16.8
  Top Layer w0.127: CN22.B8@5.814,49.032 6.469,49.032 v2(6.566,49.131) ; v1(8.636,61.671) CN19.12@8.636,63.63
  Bottom Layer w0.127: v2(6.566,49.131) 8.735,51.298 8.735,55.801 9.37,56.436 9.37,60.937 v1(8.636,61.671)
C1_TX1+: CN19.3 CN22.A2 | length 17.4
  Top Layer w0.155: CN19.3@3.556,59.56 3.556,58.44 4,57.996 4,57.683 v1(3.721,57.407) ; CN22.A2@7.416,50.284 7.476,50.224 7.954,50.224 8.61,50.88 8.61,52.72 9.037,53.147 9.608,53.147 v1@9.773,53.312
  L4_SIG w0.13: v1(3.721,57.407) 4,57.127 4,56.218 4.417,55.801 6.195,55.801 6.373,55.623 6.632,55.623 6.81,55.801 7.069,55.801 7.247,55.623 7.506,55.623 7.683,55.801 8.197,55.801 8.39,55.608 8.39,55.359 8.572,55.176 8.821,55.176 9.004,54.994 9.004,54.745 9.187,54.562 9.436,54.562 10.259,53.739 10.259,53.292 10.112,53.144 9.936,53.144 v1(9.771,53.31)
C1_TX1-: CN19.5 CN22.A3 | length 17.5
  Top Layer w0.155: v1(4.658,57.407) 4.381,57.683 4.381,58.052 4.826,58.496 CN19.5@4.826,59.56 ; CN22.A3@7.414,49.784 CN22.A3@7.416,49.784 7.476,49.843 8.112,49.843 8.991,50.722 8.991,52.562 9.195,52.766 9.608,52.766 v1@9.773,52.6 ; CN22.A3@7.416,49.784 CN22.A3@7.416,49.784
  L4_SIG w0.13: v1(4.658,57.407) 4.381,57.127 4.381,56.375 4.575,56.182 8.354,56.182 10.64,53.896 10.64,53.134 10.269,52.763 9.936,52.763 v1(9.771,52.598)
C1_TX2+: CN19.18 CN22.B2 | length 30.1
  Top Layer w0.155: CN22.B2@5.816,46.034 5.876,46.093 6.477,46.093 v2(6.566,46.004) ; v1(12.281,65.657) 12.022,65.398 12.022,65.052 12.446,64.628 CN19.18@12.446,63.63
  L4_SIG w0.13: v2(6.566,46.004) 6.655,46.093 6.805,46.093 7.054,45.844 8.615,45.844 9.354,46.584 11.994,46.584 12.672,47.261 12.672,54.404 10.386,56.69 10.386,58.311 12.002,59.926 12.002,65.378 v1(12.281,65.657)
C1_TX2-: CN19.16 CN22.B3 | length 30.1
  Top Layer w0.155: CN22.B3@5.816,46.534 5.876,46.474 6.477,46.474 v2(6.566,46.563) ; CN19.16@11.176,63.63 11.176,64.572 11.641,65.037 11.641,65.357 v1(11.344,65.657)
  L4_SIG w0.13: v2(6.566,46.563) 6.655,46.474 6.962,46.474 7.211,46.225 8.457,46.225 9.196,46.965 11.836,46.965 12.291,47.419 12.291,48.034 12.113,48.212 12.113,48.471 12.291,48.649 12.291,48.908 12.113,49.086 12.113,49.345 12.291,49.522 12.291,49.781 12.113,49.959 12.113,50.218 12.291,50.396 12.291,50.655 12.113,50.833 12.113,51.092 12.291,51.27 12.291,54.247 10.005,56.533 10.005,58.468 11.62,60.084 11.62,65.38 v1(11.344,65.657)
CAL: R228.1 T2.3 U32.3 | length 24.6
  Top Layer w0.127: T2.3@53.957,51.57 55.133,51.57 55.491,51.928 v1(56.424,51.928) ; v1(71.854,49.705) 72.807,50.658 U32.3@72.807,52.292
  Bottom Layer w0.127: v1(56.424,51.928) 58.329,51.928 59.408,53.007 70.838,53.007 72.362,51.483 72.362,50.213 v1(71.854,49.705)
